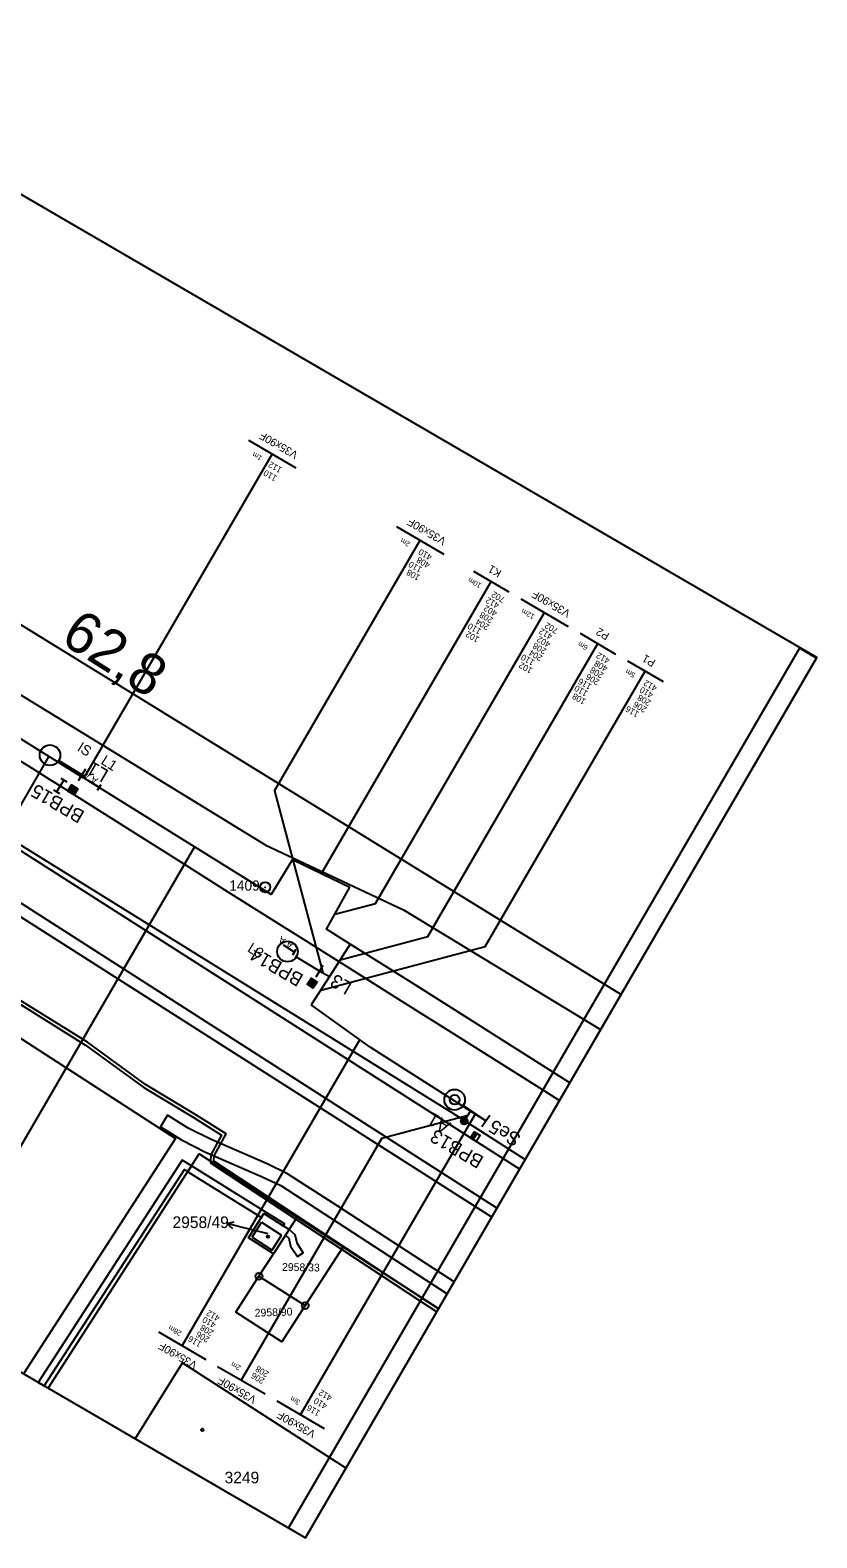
# Model space of a CAD drawing. Extents: x -621126 to -620688, y -1122470 to -1122131.
# Drawn here: x -620803 to -620688.2, y -1122470.1 to -1122250.2 of the extents above; entities that cross this region are included whole.
import ezdxf

# ---------------------------------------------------------------- set-up
doc = ezdxf.new("R2010")
doc.units = 0
for name, color, linetype in [('HranDP', 7, 'Continuous'), ('Hranice parcel', 7, 'Continuous'), ('Parcelní čísla', 7, 'Continuous'), ('Pop  PČ popisy', 7, 'Continuous'), ('Rámečky-tisk', 7, 'Continuous'), ('Vnitřní kresba', 7, 'Continuous'), ('Vrstva 1', 7, 'Continuous'), ('Vrstva 2', 7, 'Continuous'), ('Vrstva 3', 7, 'Continuous'), ('Vrstva 33', 7, 'Continuous'), ('Vrstva 6', 7, 'Continuous'), ('Vrstva 7', 7, 'Continuous'), ('Věcná břemena k části', 7, 'Continuous'), ('Značky bodu BP', 7, 'Continuous'), ('Značky budov', 7, 'Continuous')]:
    doc.layers.add(name, color=color, linetype=linetype)

msp = doc.modelspace()

# ---------------------------------------------------------------- linework, layer by layer
at = {"layer": 'HranDP'}
for points in [[(-620847.72, -1122320.67), (-620838.83, -1122326.12), (-620768.63, -1122369.09), (-620748.53, -1122378.52), (-620719.75, -1122396)], [(-620821.12, -1122358.76), (-620741.46, -1122408.09), (-620730.75, -1122414.92)]]:
    msp.add_lwpolyline(points, dxfattribs=at)
at = {"layer": 'Hranice parcel'}
for p, q in [((-620866.03, -1122298.98), (-620716.77, -1122390.88)), ((-620765.22, -1122425.14), (-620767.52, -1122428.7)), ((-620765.22, -1122425.14), (-620764.06, -1122423.34)), ((-620764.06, -1122423.34), (-620757.34, -1122427.68)), ((-620769.63, -1122431.96), (-620767.52, -1122428.7)), ((-620757.34, -1122427.68), (-620762.87, -1122436.24)), ((-620757.34, -1122427.68), (-620743.4, -1122436.68)), ((-620769.63, -1122431.96), (-620762.87, -1122436.24))]:
    msp.add_line(p, q, dxfattribs=at)
for points in [[(-620847.72, -1122320.67), (-620838.83, -1122326.12), (-620768.63, -1122369.09), (-620748.53, -1122378.52), (-620719.75, -1122396)], [(-620821.12, -1122358.76), (-620741.46, -1122408.09), (-620730.75, -1122414.92)], [(-620821.12, -1122358.76), (-620807.67, -1122367.84), (-620731.57, -1122416.33)], [(-620735.65, -1122423.34), (-620825.92, -1122365.89)], [(-620848.87, -1122368.55), (-620781.81, -1122411.87), (-620803.98, -1122446.19)], [(-620800.4, -1122448.26), (-620778.34, -1122414.11), (-620764.06, -1122423.34)], [(-620767.52, -1122428.7), (-620771.15, -1122426.36), (-620768.9, -1122422.81), (-620765.22, -1122425.14)], [(-620762.87, -1122436.24), (-620766.29, -1122441.54), (-620773.01, -1122437.2), (-620769.63, -1122431.96)], [(-620787.71, -1122455.65), (-620780.78, -1122444.6), (-620756.92, -1122459.93)]]:
    msp.add_lwpolyline(points, dxfattribs=at)
at = {"layer": 'Pop  PČ popisy'}
for p, q in [((-620774.33, -1122424.27), (-620773.24, -1122424.03)), ((-620771.42, -1122425), (-620774.33, -1122424.27)), ((-620774.33, -1122424.27), (-620773.48, -1122425)), ((-620768.29, -1122425.79), (-620771.42, -1122425))]:
    msp.add_line(p, q, dxfattribs=at)
at = {"layer": 'Rámečky-tisk'}
for points in [[(-621051.28, -1122130.61), (-621125.92, -1122258.99), (-620762.84, -1122470.11)], [(-620762.84, -1122470.11), (-620688.19, -1122341.73), (-621051.28, -1122130.61)], [(-620688.26, -1122341.84), (-620690.75, -1122340.39), (-620765.33, -1122468.66)], [(-620765.33, -1122468.66), (-620762.84, -1122470.11), (-620688.26, -1122341.84)]]:
    msp.add_lwpolyline(points, dxfattribs=at)
at = {"layer": 'Vnitřní kresba'}
for p, q in [((-620810.36, -1122373.73), (-620734.88, -1122422.02)), ((-620770.64, -1122426.28), (-620769.25, -1122424.08)), ((-620769.25, -1122424.08), (-620766.31, -1122425.96)), ((-620770.64, -1122426.28), (-620767.68, -1122428.15)), ((-620767.68, -1122428.15), (-620766.31, -1122425.96))]:
    msp.add_line(p, q, dxfattribs=at)
at = {"layer": 'Vrstva 1'}
for p, q in [((-620764.72, -1122371.2), (-620756.35, -1122375.21)), ((-620756.33, -1122383.52), (-620759.35, -1122388.27)), ((-620760.76, -1122387.45), (-620759.35, -1122388.27)), ((-620759.35, -1122388.27), (-620761.98, -1122392.4)), ((-620739.67, -1122409.34), (-620738.73, -1122407.89)), ((-620736.51, -1122409.3), (-620738.73, -1122407.89))]:
    msp.add_line(p, q, dxfattribs=at)
for points in [[(-620851.64, -1122327.08), (-620843.14, -1122332.43), (-620837.63, -1122335.92), (-620832.12, -1122339.39), (-620828.02, -1122341.97), (-620823.79, -1122344.63), (-620816.97, -1122348.94), (-620810.35, -1122353.09), (-620803.86, -1122357.18), (-620803.36, -1122357.5), (-620800.13, -1122359.53), (-620798.65, -1122360.46), (-620794.42, -1122363.12), (-620788.1, -1122367.1), (-620781.12, -1122371.5), (-620774.17, -1122375.88), (-620767.51, -1122380.06), (-620763.22, -1122382.76), (-620756.39, -1122387.05), (-620748.87, -1122391.78), (-620741.59, -1122396.35), (-620734.61, -1122400.75), (-620727.79, -1122405.03), (-620725.75, -1122406.32)], [(-620795.27, -1122359.26), (-620795.68, -1122359.01), (-620806.11, -1122352.53)], [(-620795.42, -1122358.82), (-620795.12, -1122359.01), (-620795.27, -1122359.26)], [(-620764.72, -1122371.2), (-620767.85, -1122376.3), (-620794.6, -1122359.68), (-620795.27, -1122359.26)], [(-620756.33, -1122383.52), (-620759.75, -1122381.36), (-620756.35, -1122375.21)], [(-620724.25, -1122403.74), (-620747.38, -1122389.13), (-620756.33, -1122383.52)], [(-620738.73, -1122407.89), (-620753.37, -1122398.54), (-620761.98, -1122392.4)]]:
    msp.add_lwpolyline(points, dxfattribs=at)
at = {"layer": 'Vrstva 2'}
for p, q in [((-620798.85, -1122356.75), (-620795.42, -1122358.82)), ((-620795.94, -1122359.68), (-620794.91, -1122357.96)), ((-620796.1, -1122360.91), (-620797.46, -1122361.25)), ((-620796.18, -1122360.8), (-620797.45, -1122361.11)), ((-620796.33, -1122360.7), (-620797.35, -1122360.95)), ((-620796.2, -1122361.07), (-620797.3, -1122361.34)), ((-620796.49, -1122360.6), (-620797.26, -1122360.79)), ((-620796.65, -1122360.51), (-620797.16, -1122360.63)), ((-620796.29, -1122361.23), (-620797.14, -1122361.44)), ((-620796.81, -1122360.41), (-620797.06, -1122360.48)), ((-620796.39, -1122361.39), (-620796.98, -1122361.54)), ((-620796.49, -1122361.55), (-620796.82, -1122361.63)), ((-620796.58, -1122361.71), (-620796.66, -1122361.73)), ((-620764.19, -1122385.38), (-620760.76, -1122387.45)), ((-620761.28, -1122388.31), (-620760.25, -1122386.59)), ((-620761.17, -1122389.11), (-620762.54, -1122389.38)), ((-620761.23, -1122388.99), (-620762.52, -1122389.24)), ((-620761.39, -1122388.88), (-620762.42, -1122389.09)), ((-620761.27, -1122389.26), (-620762.38, -1122389.48)), ((-620761.54, -1122388.78), (-620762.31, -1122388.93)), ((-620761.37, -1122389.42), (-620762.23, -1122389.59)), ((-620761.7, -1122388.68), (-620762.21, -1122388.78)), ((-620761.85, -1122388.57), (-620762.11, -1122388.63)), ((-620761.48, -1122389.57), (-620762.07, -1122389.69)), ((-620761.58, -1122389.72), (-620761.92, -1122389.79)), ((-620761.68, -1122389.88), (-620761.76, -1122389.9)), ((-620739.82, -1122407.06), (-620736.51, -1122409.3)), ((-620740.08, -1122409.62), (-620740.05, -1122409.03)), ((-620739.89, -1122409.79), (-620739.84, -1122408.88)), ((-620739.69, -1122409.84), (-620739.64, -1122408.85)), ((-620739.49, -1122409.81), (-620739.44, -1122408.9)), ((-620739.28, -1122409.66), (-620739.25, -1122409.07)), ((-620737.07, -1122410.13), (-620735.95, -1122408.48)), ((-620738.08, -1122411.66), (-620738.72, -1122411.79)), ((-620737.98, -1122411.5), (-620738.71, -1122411.65)), ((-620737.88, -1122411.35), (-620738.61, -1122411.5)), ((-620738.18, -1122411.81), (-620738.57, -1122411.89)), ((-620737.78, -1122411.19), (-620738.5, -1122411.34)), ((-620738.29, -1122411.97), (-620738.41, -1122412)), ((-620737.89, -1122411.08), (-620738.4, -1122411.19)), ((-620738.05, -1122410.98), (-620738.3, -1122411.03))]:
    msp.add_line(p, q, dxfattribs=at)
for points in [[(-620796.61, -1122361.76), (-620797.51, -1122361.22), (-620796.97, -1122360.32), (-620796.07, -1122360.86)], [(-620796.61, -1122361.76), (-620797.51, -1122361.22), (-620796.97, -1122360.32), (-620796.07, -1122360.86)], [(-620761.72, -1122389.93), (-620762.59, -1122389.35), (-620762.01, -1122388.47), (-620761.13, -1122389.06)], [(-620761.72, -1122389.93), (-620762.59, -1122389.35), (-620762.01, -1122388.47), (-620761.13, -1122389.06)], [(-620738.34, -1122412.04), (-620738.78, -1122411.76), (-620738.2, -1122410.88), (-620737.76, -1122411.17)], [(-620738.34, -1122412.04), (-620738.78, -1122411.76), (-620738.2, -1122410.88), (-620737.76, -1122411.17)], [(-620737.9, -1122412.33), (-620738.78, -1122411.76), (-620738.2, -1122410.88), (-620737.32, -1122411.45)]]:
    msp.add_lwpolyline(points, close=True, dxfattribs=at)
for centre, radius in [((-620800.13, -1122355.98), 1.5), ((-620765.47, -1122384.61), 1.5), ((-620741.06, -1122406.22), 1.5), ((-620741.06, -1122406.22), 0.7), ((-620739.67, -1122409.34), 0.5)]:
    msp.add_circle(centre, radius, dxfattribs=at)
at = {"layer": 'Vrstva 3'}
for p, q in [((-620798.54, -1122359.35), (-620797.69, -1122359.88)), ((-620799.61, -1122361.04), (-620798.76, -1122361.57)), ((-620798.12, -1122359.61), (-620799.18, -1122361.3))]:
    msp.add_line(p, q, dxfattribs=at)
at = {"layer": 'Vrstva 33'}
for p, q in [((-620771.17, -1122310.05), (-620764.25, -1122314.08)), ((-620794.9, -1122358.83), (-620767.71, -1122312.06)), ((-620749.56, -1122322.62), (-620742.64, -1122326.64)), ((-620767.34, -1122361.17), (-620746.1, -1122324.63)), ((-620760.48, -1122373.23), (-620735.72, -1122330.66)), ((-620738.32, -1122329.15), (-620733.13, -1122332.17)), ((-620752.6, -1122377.6), (-620727.94, -1122335.19)), ((-620731.4, -1122333.18), (-620724.49, -1122337.2)), ((-620722.76, -1122338.2), (-620717.57, -1122341.22)), ((-620744.99, -1122382.41), (-620720.16, -1122339.71)), ((-620736.6, -1122383.89), (-620713.25, -1122343.73)), ((-620715.84, -1122342.22), (-620710.65, -1122345.24)), ((-620800.28, -1122356.14), (-620832.72, -1122411.92)), ((-620795.25, -1122358.92), (-620794.9, -1122358.83)), ((-620767.34, -1122361.17), (-620760.32, -1122387.71)), ((-620779.04, -1122369.35), (-620811.1, -1122424.49)), ((-620758.54, -1122379.17), (-620752.6, -1122377.6)), ((-620757.78, -1122385.8), (-620744.99, -1122382.41)), ((-620760.61, -1122390.25), (-620736.6, -1122383.89)), ((-620754.89, -1122397.45), (-620780.85, -1122442.08)), ((-620738.07, -1122408.31), (-620763.56, -1122452.13)), ((-620751.67, -1122411.8), (-620739.11, -1122408.47)), ((-620751.67, -1122411.8), (-620772.2, -1122447.11)), ((-620784.3, -1122440.07), (-620777.39, -1122444.09)), ((-620775.66, -1122445.1), (-620768.74, -1122449.12)), ((-620767.01, -1122450.12), (-620760.1, -1122454.15))]:
    msp.add_line(p, q, dxfattribs=at)
at = {"layer": 'Vrstva 6'}
for p, q in [((-620794.6, -1122359.6), (-620792.93, -1122360.66)), ((-620793.19, -1122361.08), (-620792.66, -1122360.23)), ((-620766.11, -1122383.64), (-620764.44, -1122384.69)), ((-620764.7, -1122385.11), (-620764.17, -1122384.26))]:
    msp.add_line(p, q, dxfattribs=at)
at = {"layer": 'Věcná břemena k části'}
for p, q in [((-620742.13, -1122434.5), (-620741.13, -1122432.77)), ((-620743.66, -1122437.13), (-620743.41, -1122436.7)), ((-620801.83, -1122447.43), (-620800.96, -1122447.94))]:
    msp.add_line(p, q, dxfattribs=at)
for points in [[(-620806.44, -1122391.09), (-620794.95, -1122398.24), (-620786.45, -1122404.42), (-620779.08, -1122408.85), (-620775.09, -1122411.38), (-620776.65, -1122414.26), (-620776.7, -1122415.17), (-620748.87, -1122433.15), (-620776.2, -1122415.17), (-620776.15, -1122414.4), (-620774.43, -1122411.2), (-620778.82, -1122408.43), (-620786.17, -1122404), (-620794.67, -1122397.82), (-620806.18, -1122390.67)], [(-620741.13, -1122432.77), (-620758.09, -1122421.75), (-620765.44, -1122417.01), (-620768.43, -1122415.58), (-620776.6, -1122412.03), (-620779.94, -1122410.35), (-620782.95, -1122408.48), (-620784.01, -1122410.19), (-620780.92, -1122412.09), (-620777.44, -1122413.85), (-620769.25, -1122417.4), (-620766.42, -1122418.75), (-620759.17, -1122423.43), (-620742.13, -1122434.5)], [(-620800.96, -1122447.94), (-620780.51, -1122416.41), (-620780.02, -1122416.71), (-620779.48, -1122415.87), (-620780.82, -1122415.04), (-620801.83, -1122447.43)], [(-620743.41, -1122436.7), (-620745.63, -1122435.28), (-620748.87, -1122433.15), (-620776.7, -1122415.17), (-620776.72, -1122415.43), (-620764.25, -1122423.63), (-620757.57, -1122428.03), (-620745.91, -1122435.7), (-620743.66, -1122437.13)]]:
    msp.add_lwpolyline(points, dxfattribs=at)
for points in [[(-620779.48, -1122415.87), (-620780.02, -1122416.71), (-620769.26, -1122423.38), (-620768.9, -1122422.81), (-620768.58, -1122423.01), (-620766.07, -1122424.6), (-620765.88, -1122424.3)], [(-620765.22, -1122425.14), (-620765.76, -1122425.98), (-620765.28, -1122426.39), (-620765.01, -1122427.55), (-620763.99, -1122429.09), (-620763.16, -1122428.53), (-620764.07, -1122427.15), (-620764.36, -1122425.91)]]:
    msp.add_lwpolyline(points, close=True, dxfattribs=at)
at = {"layer": 'Značky bodu BP'}
for centre, radius in [((-620768.72, -1122375.23), 0.75), ((-620768.72, -1122375.23), 0.03), ((-620769.63, -1122431.96), 0.5), ((-620769.63, -1122431.96), 0.0303), ((-620762.87, -1122436.24), 0.5), ((-620762.87, -1122436.24), 0.0303)]:
    msp.add_circle(centre, radius, dxfattribs=at)
at = {"layer": 'Značky budov'}
for centre in [(-620768.32, -1122426.2), (-620777.91, -1122454.36)]:
    msp.add_circle(centre, 0.175, dxfattribs=at)

# ---------------------------------------------------------------- texts
at = {"layer": 'Parcelní čísla'}
for s, p in [('2958/49', (-620782.24, -1122424.93)), ('3249', (-620774.64, -1122462.16))]:
    msp.add_text(s, height=1.7, dxfattribs=at).set_placement(p)
for s, rotation, p in [('2958/33', 359, (-620766.26, -1122431.17)), ('2958/90', 2, (-620770.22, -1122437.87))]:
    msp.add_text(s, height=1.139, rotation=rotation, dxfattribs=at).set_placement(p)
at = {"layer": 'Vrstva 3'}
for s, height, rotation, p in [('IS', 1.5, 327.7899, (-620796.27, -1122355.23)), ('L1', 2, 149.8236, (-620791.41, -1122358.28)), ('BPB15', 2, 149.8236, (-620794.92, -1122364.27)), ('BPB14', 2, 149.8236, (-620762.97, -1122388.1)), ('L3', 2, 149.8236, (-620755.87, -1122389.29)), ('A1', 2, 149.8236, (-620741.5, -1122409.63)), ('Se5', 2, 148.8786, (-620731.22, -1122411.47)), ('BPB13', 2, 149.8236, (-620736.66, -1122414.63))]:
    msp.add_text(s, height=height, rotation=rotation, dxfattribs=at).set_placement(p)
at = {"layer": 'Vrstva 33'}
for s, height, p in [('V35x90F', 1.15, (-620763.81, -1122311.84)), ('1m', 0.75, (-620769.08, -1122312.43)), ('112', 0.9, (-620766.18, -1122314.11)), ('110', 0.9, (-620766.89, -1122315.32)), ('V35x90F', 1.15, (-620742.2, -1122324.41)), ('2m', 0.75, (-620747.47, -1122324.99)), ('410', 0.9, (-620744.27, -1122326.85)), ('110', 0.9, (-620745.73, -1122328.66)), ('408', 0.9, (-620744.56, -1122328.01)), ('K1', 1.15, (-620734.11, -1122329.12)), ('108', 0.9, (-620746.03, -1122329.82)), ('10m', 0.75, (-620737.09, -1122331.02)), ('412', 0.9, (-620734.46, -1122333.89)), ('702', 0.9, (-620733.63, -1122333.04)), ('V35x90F', 1.15, (-620724.05, -1122334.96)), ('208', 0.9, (-620735.37, -1122336.02)), ('402', 0.9, (-620734.76, -1122335.04)), ('12m', 0.75, (-620729.31, -1122335.55)), ('110', 0.9, (-620737.09, -1122337.67)), ('204', 0.9, (-620735.92, -1122337.03)), ('412', 0.9, (-620726.68, -1122338.41)), ('702', 0.9, (-620725.85, -1122337.56)), ('P2', 1.15, (-620718.36, -1122338.27)), ('102', 0.9, (-620737.39, -1122338.84)), ('208', 0.9, (-620727.59, -1122340.54)), ('402', 0.9, (-620726.98, -1122339.56)), ('6m', 0.75, (-620721.53, -1122340.07)), ('110', 0.9, (-620729.31, -1122342.2)), ('204', 0.9, (-620728.14, -1122341.55)), ('412', 0.9, (-620718.32, -1122341.94)), ('P1', 1.15, (-620711.63, -1122342.18)), ('102', 0.9, (-620729.61, -1122343.36)), ('208', 0.9, (-620719.23, -1122344.07)), ('408', 0.9, (-620718.62, -1122343.09)), ('5m', 0.75, (-620714.61, -1122344.09)), ('110', 0.9, (-620721.53, -1122346.72)), ('116', 0.9, (-620720.98, -1122345.72)), ('206', 0.9, (-620719.84, -1122345.05)), ('410', 0.9, (-620711.99, -1122346.95)), ('412', 0.9, (-620711.41, -1122345.96)), ('108', 0.9, (-620721.83, -1122347.88)), ('206', 0.9, (-620712.93, -1122349.07)), ('208', 0.9, (-620712.32, -1122348.09)), ('116', 0.9, (-620714.06, -1122349.74)), ('410', 0.9, (-620775.82, -1122438.81)), ('412', 0.9, (-620775.23, -1122437.83)), ('28m', 0.75, (-620780.83, -1122440.07)), ('116', 0.9, (-620777.89, -1122441.6)), ('206', 0.9, (-620776.75, -1122440.93)), ('208', 0.9, (-620776.14, -1122439.96)), ('V35x90F', 1.15, (-620778.53, -1122444.58)), ('2m', 0.75, (-620772.19, -1122445.09)), ('208', 0.9, (-620768.08, -1122445.98)), ('V35x90F', 1.15, (-620769.89, -1122449.61)), ('206', 0.9, (-620768.69, -1122446.95)), ('3m', 0.75, (-620763.54, -1122450.12)), ('412', 0.9, (-620758.85, -1122449.44)), ('116', 0.9, (-620760.6, -1122451.66)), ('410', 0.9, (-620759.56, -1122450.64)), ('V35x90F', 1.15, (-620761.24, -1122454.64))]:
    msp.add_text(s, height=height, rotation=149.8236, dxfattribs=at).set_placement(p)
at = {"layer": 'Vrstva 6'}
for s, height, rotation, p in [('L1', 1.5, 327.7824, (-620792.81, -1122357.16)), ('  A A ', 1, 147.7824, (-620792.39, -1122359.81)), ('L3', 1.5, 327.8824, (-620771.42, -1122384.51)), ('  A A ', 1, 147.8824, (-620763.9, -1122383.84))]:
    msp.add_text(s, height=height, rotation=rotation, dxfattribs=at).set_placement(p)
at = {"layer": 'Vrstva 7'}
msp.add_text('62,8', height=6, rotation=327.7881, dxfattribs=at).set_placement((-620798.8, -1122339.47))
at = {"layer": 'Značky bodu BP'}
msp.add_text('1409', height=1.5, dxfattribs=at).set_placement((-620773.97, -1122375.73))

doc.saveas('drawing.dxf')
